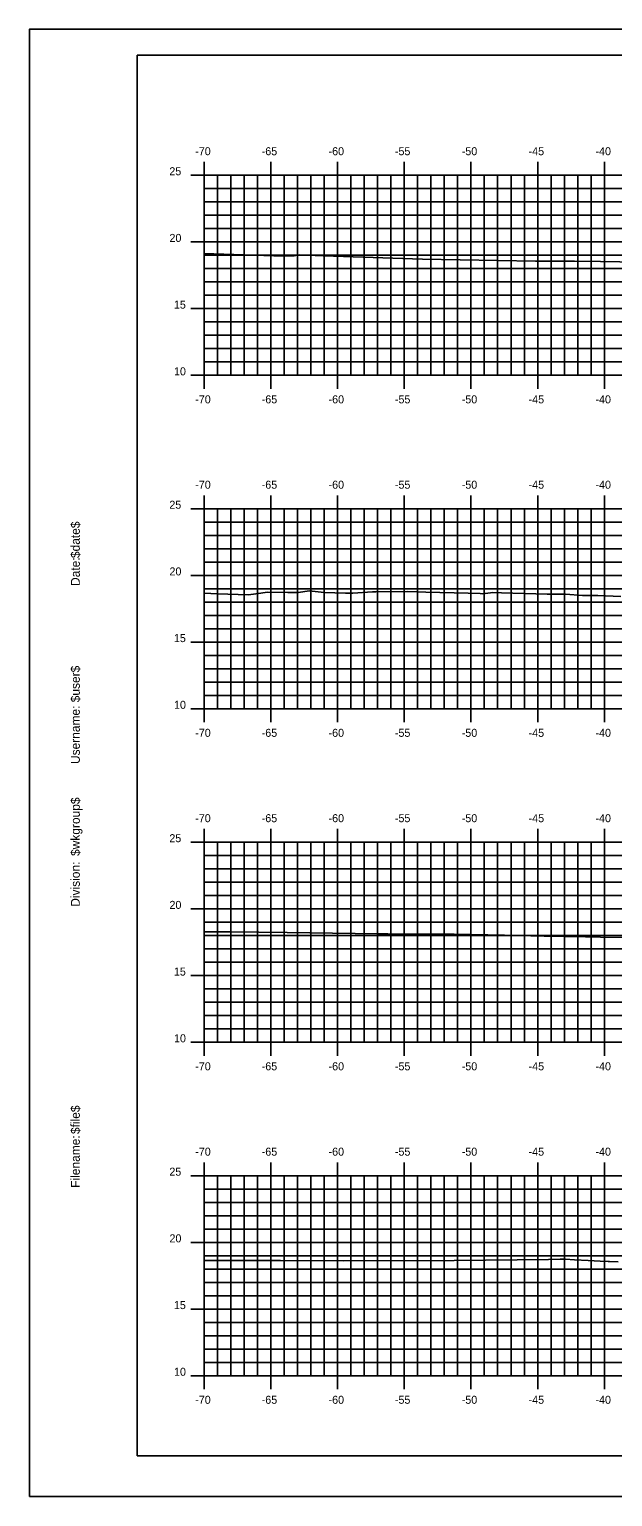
# Model space of a CAD drawing. Extents: x 1023237 to 1023407, y 394697 to 394807.
# Drawn here: x 1023236.6 to 1023280.3, y 394696.5 to 394806.5 of the extents above; entities that cross this region are included whole.
import ezdxf

# ---------------------------------------------------------------- set-up
doc = ezdxf.new("R2010")
doc.units = 0
for name, color, linetype in [('BORDER', 7, 'Continuous'), ('H_V ANNOTATION', 7, 'Continuous'), ('MAJOR', 7, 'Continuous'), ('MINOR', 7, 'Continuous'), ('PLOT BOUNDARY', 7, 'Continuous'), ('S_Roadway_Centerline', 7, 'Continuous')]:
    doc.layers.add(name, color=color, linetype=linetype)

msp = doc.modelspace()

# ---------------------------------------------------------------- linework, layer by layer
at = {"layer": 'BORDER'}
for p, q in [((1023404.66, 394804.61), (1023244.66, 394804.61)), ((1023244.66, 394804.61), (1023244.66, 394699.61)), ((1023244.66, 394699.61), (1023404.66, 394699.61))]:
    msp.add_line(p, q, dxfattribs=at)
at = {"layer": 'MAJOR'}
for p, q in [((1023249.66, 394796.61), (1023249.66, 394795.61)), ((1023254.66, 394796.61), (1023254.66, 394795.61)), ((1023259.66, 394796.61), (1023259.66, 394795.61)), ((1023264.66, 394796.61), (1023264.66, 394795.61)), ((1023269.66, 394796.61), (1023269.66, 394795.61)), ((1023274.66, 394796.61), (1023274.66, 394795.61)), ((1023279.66, 394796.61), (1023279.66, 394795.61)), ((1023248.66, 394795.61), (1023249.66, 394795.61)), ((1023249.66, 394795.61), (1023389.66, 394795.61)), ((1023249.66, 394780.61), (1023249.66, 394795.61)), ((1023254.66, 394780.61), (1023254.66, 394795.61)), ((1023259.66, 394780.61), (1023259.66, 394795.61)), ((1023264.66, 394780.61), (1023264.66, 394795.61)), ((1023269.66, 394780.61), (1023269.66, 394795.61)), ((1023274.66, 394780.61), (1023274.66, 394795.61)), ((1023279.66, 394780.61), (1023279.66, 394795.61)), ((1023248.66, 394790.61), (1023249.66, 394790.61)), ((1023249.66, 394790.61), (1023389.66, 394790.61)), ((1023248.66, 394785.61), (1023249.66, 394785.61)), ((1023249.66, 394785.61), (1023389.66, 394785.61)), ((1023248.66, 394780.61), (1023249.66, 394780.61)), ((1023249.66, 394780.61), (1023389.66, 394780.61)), ((1023249.66, 394779.6), (1023249.66, 394780.61)), ((1023254.66, 394779.6), (1023254.66, 394780.61)), ((1023259.66, 394779.6), (1023259.66, 394780.61)), ((1023264.66, 394779.6), (1023264.66, 394780.61)), ((1023269.66, 394779.6), (1023269.66, 394780.61)), ((1023274.66, 394779.6), (1023274.66, 394780.61)), ((1023279.66, 394779.6), (1023279.66, 394780.61)), ((1023249.66, 394771.61), (1023249.66, 394770.61)), ((1023254.66, 394771.61), (1023254.66, 394770.61)), ((1023259.66, 394771.61), (1023259.66, 394770.61)), ((1023264.66, 394771.61), (1023264.66, 394770.61)), ((1023269.66, 394771.61), (1023269.66, 394770.61)), ((1023274.66, 394771.61), (1023274.66, 394770.61)), ((1023279.66, 394771.61), (1023279.66, 394770.61)), ((1023248.66, 394770.61), (1023249.66, 394770.61)), ((1023249.66, 394770.61), (1023389.66, 394770.61)), ((1023249.66, 394755.61), (1023249.66, 394770.61)), ((1023254.66, 394755.61), (1023254.66, 394770.61)), ((1023259.66, 394755.61), (1023259.66, 394770.61)), ((1023264.66, 394755.61), (1023264.66, 394770.61)), ((1023269.66, 394755.61), (1023269.66, 394770.61)), ((1023274.66, 394755.61), (1023274.66, 394770.61)), ((1023279.66, 394755.61), (1023279.66, 394770.61)), ((1023248.66, 394765.61), (1023249.66, 394765.61)), ((1023249.66, 394765.61), (1023389.66, 394765.61)), ((1023248.66, 394760.61), (1023249.66, 394760.61)), ((1023249.66, 394760.61), (1023389.66, 394760.61)), ((1023248.66, 394755.61), (1023249.66, 394755.61)), ((1023249.66, 394755.61), (1023389.66, 394755.61)), ((1023249.66, 394754.6), (1023249.66, 394755.61)), ((1023254.66, 394754.6), (1023254.66, 394755.61)), ((1023259.66, 394754.6), (1023259.66, 394755.61)), ((1023264.66, 394754.6), (1023264.66, 394755.61)), ((1023269.66, 394754.6), (1023269.66, 394755.61)), ((1023274.66, 394754.6), (1023274.66, 394755.61)), ((1023279.66, 394754.6), (1023279.66, 394755.61)), ((1023249.66, 394746.61), (1023249.66, 394745.61)), ((1023254.66, 394746.61), (1023254.66, 394745.61)), ((1023259.66, 394746.61), (1023259.66, 394745.61)), ((1023264.66, 394746.61), (1023264.66, 394745.61)), ((1023269.66, 394746.61), (1023269.66, 394745.61)), ((1023274.66, 394746.61), (1023274.66, 394745.61)), ((1023279.66, 394746.61), (1023279.66, 394745.61)), ((1023248.66, 394745.61), (1023249.66, 394745.61)), ((1023249.66, 394745.61), (1023389.66, 394745.61)), ((1023249.66, 394730.61), (1023249.66, 394745.61)), ((1023254.66, 394730.61), (1023254.66, 394745.61)), ((1023259.66, 394730.61), (1023259.66, 394745.61)), ((1023264.66, 394730.61), (1023264.66, 394745.61)), ((1023269.66, 394730.61), (1023269.66, 394745.61)), ((1023274.66, 394730.61), (1023274.66, 394745.61)), ((1023279.66, 394730.61), (1023279.66, 394745.61)), ((1023248.66, 394740.61), (1023249.66, 394740.61)), ((1023249.66, 394740.61), (1023389.66, 394740.61)), ((1023248.66, 394735.61), (1023249.66, 394735.61)), ((1023249.66, 394735.61), (1023389.66, 394735.61)), ((1023248.66, 394730.61), (1023249.66, 394730.61)), ((1023249.66, 394730.61), (1023389.66, 394730.61)), ((1023249.66, 394729.6), (1023249.66, 394730.61)), ((1023254.66, 394729.6), (1023254.66, 394730.61)), ((1023259.66, 394729.6), (1023259.66, 394730.61)), ((1023264.66, 394729.6), (1023264.66, 394730.61)), ((1023269.66, 394729.6), (1023269.66, 394730.61)), ((1023274.66, 394729.6), (1023274.66, 394730.61)), ((1023279.66, 394729.6), (1023279.66, 394730.61)), ((1023249.66, 394721.61), (1023249.66, 394720.61)), ((1023254.66, 394721.61), (1023254.66, 394720.61)), ((1023259.66, 394721.61), (1023259.66, 394720.61)), ((1023264.66, 394721.61), (1023264.66, 394720.61)), ((1023269.66, 394721.61), (1023269.66, 394720.61)), ((1023274.66, 394721.61), (1023274.66, 394720.61)), ((1023279.66, 394721.61), (1023279.66, 394720.61)), ((1023248.66, 394720.61), (1023249.66, 394720.61)), ((1023249.66, 394720.61), (1023389.66, 394720.61)), ((1023249.66, 394705.61), (1023249.66, 394720.61)), ((1023254.66, 394705.61), (1023254.66, 394720.61)), ((1023259.66, 394705.61), (1023259.66, 394720.61)), ((1023264.66, 394705.61), (1023264.66, 394720.61)), ((1023269.66, 394705.61), (1023269.66, 394720.61)), ((1023274.66, 394705.61), (1023274.66, 394720.61)), ((1023279.66, 394705.61), (1023279.66, 394720.61)), ((1023248.66, 394715.61), (1023249.66, 394715.61)), ((1023249.66, 394715.61), (1023389.66, 394715.61)), ((1023248.66, 394710.61), (1023249.66, 394710.61)), ((1023249.66, 394710.61), (1023389.66, 394710.61)), ((1023248.66, 394705.61), (1023249.66, 394705.61)), ((1023249.66, 394705.61), (1023389.66, 394705.61)), ((1023249.66, 394704.6), (1023249.66, 394705.61)), ((1023254.66, 394704.6), (1023254.66, 394705.61)), ((1023259.66, 394704.6), (1023259.66, 394705.61)), ((1023264.66, 394704.6), (1023264.66, 394705.61)), ((1023269.66, 394704.6), (1023269.66, 394705.61)), ((1023274.66, 394704.6), (1023274.66, 394705.61)), ((1023279.66, 394704.6), (1023279.66, 394705.61))]:
    msp.add_line(p, q, dxfattribs=at)
at = {"layer": 'MINOR'}
for p, q in [((1023250.66, 394780.61), (1023250.66, 394795.61)), ((1023251.66, 394780.61), (1023251.66, 394795.61)), ((1023252.66, 394780.61), (1023252.66, 394795.61)), ((1023253.66, 394780.61), (1023253.66, 394795.61)), ((1023255.66, 394780.61), (1023255.66, 394795.61)), ((1023256.66, 394780.61), (1023256.66, 394795.61)), ((1023257.66, 394780.61), (1023257.66, 394795.61)), ((1023258.66, 394780.61), (1023258.66, 394795.61)), ((1023260.66, 394780.61), (1023260.66, 394795.61)), ((1023261.66, 394780.61), (1023261.66, 394795.61)), ((1023262.66, 394780.61), (1023262.66, 394795.61)), ((1023263.66, 394780.61), (1023263.66, 394795.61)), ((1023265.66, 394780.61), (1023265.66, 394795.61)), ((1023266.66, 394780.61), (1023266.66, 394795.61)), ((1023267.66, 394780.61), (1023267.66, 394795.61)), ((1023268.66, 394780.61), (1023268.66, 394795.61)), ((1023270.66, 394780.61), (1023270.66, 394795.61)), ((1023271.66, 394780.61), (1023271.66, 394795.61)), ((1023272.66, 394780.61), (1023272.66, 394795.61)), ((1023273.66, 394780.61), (1023273.66, 394795.61)), ((1023275.66, 394780.61), (1023275.66, 394795.61)), ((1023276.66, 394780.61), (1023276.66, 394795.61)), ((1023277.66, 394780.61), (1023277.66, 394795.61)), ((1023278.66, 394780.61), (1023278.66, 394795.61)), ((1023249.66, 394794.61), (1023389.66, 394794.61)), ((1023249.66, 394794.61), (1023250.67, 394794.61)), ((1023249.66, 394793.61), (1023389.66, 394793.61)), ((1023249.66, 394793.61), (1023250.67, 394793.61)), ((1023249.66, 394792.61), (1023389.66, 394792.61)), ((1023249.66, 394792.61), (1023250.67, 394792.61)), ((1023249.66, 394791.61), (1023389.66, 394791.61)), ((1023249.66, 394791.61), (1023250.67, 394791.61)), ((1023249.66, 394789.61), (1023389.66, 394789.61)), ((1023249.66, 394789.61), (1023250.67, 394789.61)), ((1023249.66, 394788.61), (1023389.66, 394788.61)), ((1023249.66, 394788.61), (1023250.67, 394788.61)), ((1023249.66, 394787.61), (1023389.66, 394787.61)), ((1023249.66, 394787.61), (1023250.67, 394787.61)), ((1023249.66, 394786.61), (1023389.66, 394786.61)), ((1023249.66, 394786.61), (1023250.67, 394786.61)), ((1023249.66, 394784.61), (1023389.66, 394784.61)), ((1023249.66, 394784.61), (1023250.67, 394784.61)), ((1023249.66, 394783.61), (1023389.66, 394783.61)), ((1023249.66, 394783.61), (1023250.67, 394783.61)), ((1023249.66, 394782.61), (1023389.66, 394782.61)), ((1023249.66, 394782.61), (1023250.67, 394782.61)), ((1023249.66, 394781.61), (1023389.66, 394781.61)), ((1023249.66, 394781.61), (1023250.67, 394781.61)), ((1023250.66, 394755.61), (1023250.66, 394770.61)), ((1023251.66, 394755.61), (1023251.66, 394770.61)), ((1023252.66, 394755.61), (1023252.66, 394770.61)), ((1023253.66, 394755.61), (1023253.66, 394770.61)), ((1023255.66, 394755.61), (1023255.66, 394770.61)), ((1023256.66, 394755.61), (1023256.66, 394770.61)), ((1023257.66, 394755.61), (1023257.66, 394770.61)), ((1023258.66, 394755.61), (1023258.66, 394770.61)), ((1023260.66, 394755.61), (1023260.66, 394770.61)), ((1023261.66, 394755.61), (1023261.66, 394770.61)), ((1023262.66, 394755.61), (1023262.66, 394770.61)), ((1023263.66, 394755.61), (1023263.66, 394770.61)), ((1023265.66, 394755.61), (1023265.66, 394770.61)), ((1023266.66, 394755.61), (1023266.66, 394770.61)), ((1023267.66, 394755.61), (1023267.66, 394770.61)), ((1023268.66, 394755.61), (1023268.66, 394770.61)), ((1023270.66, 394755.61), (1023270.66, 394770.61)), ((1023271.66, 394755.61), (1023271.66, 394770.61)), ((1023272.66, 394755.61), (1023272.66, 394770.61)), ((1023273.66, 394755.61), (1023273.66, 394770.61)), ((1023275.66, 394755.61), (1023275.66, 394770.61)), ((1023276.66, 394755.61), (1023276.66, 394770.61)), ((1023277.66, 394755.61), (1023277.66, 394770.61)), ((1023278.66, 394755.61), (1023278.66, 394770.61)), ((1023249.66, 394769.61), (1023389.66, 394769.61)), ((1023249.66, 394769.61), (1023250.67, 394769.61)), ((1023249.66, 394768.61), (1023389.66, 394768.61)), ((1023249.66, 394768.61), (1023250.67, 394768.61)), ((1023249.66, 394767.61), (1023389.66, 394767.61)), ((1023249.66, 394767.61), (1023250.67, 394767.61)), ((1023249.66, 394766.61), (1023389.66, 394766.61)), ((1023249.66, 394766.61), (1023250.67, 394766.61)), ((1023249.66, 394764.61), (1023389.66, 394764.61)), ((1023249.66, 394764.61), (1023250.67, 394764.61)), ((1023249.66, 394763.61), (1023389.66, 394763.61)), ((1023249.66, 394763.61), (1023250.67, 394763.61)), ((1023249.66, 394762.61), (1023389.66, 394762.61)), ((1023249.66, 394762.61), (1023250.67, 394762.61)), ((1023249.66, 394761.61), (1023389.66, 394761.61)), ((1023249.66, 394761.61), (1023250.67, 394761.61)), ((1023249.66, 394759.61), (1023389.66, 394759.61)), ((1023249.66, 394759.61), (1023250.67, 394759.61)), ((1023249.66, 394758.61), (1023389.66, 394758.61)), ((1023249.66, 394758.61), (1023250.67, 394758.61)), ((1023249.66, 394757.61), (1023389.66, 394757.61)), ((1023249.66, 394757.61), (1023250.67, 394757.61)), ((1023249.66, 394756.61), (1023389.66, 394756.61)), ((1023249.66, 394756.61), (1023250.67, 394756.61)), ((1023250.66, 394730.61), (1023250.66, 394745.61)), ((1023251.66, 394730.61), (1023251.66, 394745.61)), ((1023252.66, 394730.61), (1023252.66, 394745.61)), ((1023253.66, 394730.61), (1023253.66, 394745.61)), ((1023255.66, 394730.61), (1023255.66, 394745.61)), ((1023256.66, 394730.61), (1023256.66, 394745.61)), ((1023257.66, 394730.61), (1023257.66, 394745.61)), ((1023258.66, 394730.61), (1023258.66, 394745.61)), ((1023260.66, 394730.61), (1023260.66, 394745.61)), ((1023261.66, 394730.61), (1023261.66, 394745.61)), ((1023262.66, 394730.61), (1023262.66, 394745.61)), ((1023263.66, 394730.61), (1023263.66, 394745.61)), ((1023265.66, 394730.61), (1023265.66, 394745.61)), ((1023266.66, 394730.61), (1023266.66, 394745.61)), ((1023267.66, 394730.61), (1023267.66, 394745.61)), ((1023268.66, 394730.61), (1023268.66, 394745.61)), ((1023270.66, 394730.61), (1023270.66, 394745.61)), ((1023271.66, 394730.61), (1023271.66, 394745.61)), ((1023272.66, 394730.61), (1023272.66, 394745.61)), ((1023273.66, 394730.61), (1023273.66, 394745.61)), ((1023275.66, 394730.61), (1023275.66, 394745.61)), ((1023276.66, 394730.61), (1023276.66, 394745.61)), ((1023277.66, 394730.61), (1023277.66, 394745.61)), ((1023278.66, 394730.61), (1023278.66, 394745.61)), ((1023249.66, 394744.61), (1023389.66, 394744.61)), ((1023249.66, 394744.61), (1023250.67, 394744.61)), ((1023249.66, 394743.61), (1023389.66, 394743.61)), ((1023249.66, 394743.61), (1023250.67, 394743.61)), ((1023249.66, 394742.61), (1023389.66, 394742.61)), ((1023249.66, 394742.61), (1023250.67, 394742.61)), ((1023249.66, 394741.61), (1023389.66, 394741.61)), ((1023249.66, 394741.61), (1023250.67, 394741.61)), ((1023249.66, 394739.61), (1023389.66, 394739.61)), ((1023249.66, 394739.61), (1023250.67, 394739.61)), ((1023249.66, 394738.61), (1023389.66, 394738.61)), ((1023249.66, 394738.61), (1023250.67, 394738.61)), ((1023249.66, 394737.61), (1023389.66, 394737.61)), ((1023249.66, 394737.61), (1023250.67, 394737.61)), ((1023249.66, 394736.61), (1023389.66, 394736.61)), ((1023249.66, 394736.61), (1023250.67, 394736.61)), ((1023249.66, 394734.61), (1023389.66, 394734.61)), ((1023249.66, 394734.61), (1023250.67, 394734.61)), ((1023249.66, 394733.61), (1023389.66, 394733.61)), ((1023249.66, 394733.61), (1023250.67, 394733.61)), ((1023249.66, 394732.61), (1023389.66, 394732.61)), ((1023249.66, 394732.61), (1023250.67, 394732.61)), ((1023249.66, 394731.61), (1023389.66, 394731.61)), ((1023249.66, 394731.61), (1023250.67, 394731.61)), ((1023249.66, 394719.61), (1023389.66, 394719.61)), ((1023249.66, 394719.61), (1023250.67, 394719.61)), ((1023250.66, 394705.61), (1023250.66, 394720.61)), ((1023251.66, 394705.61), (1023251.66, 394720.61)), ((1023252.66, 394705.61), (1023252.66, 394720.61)), ((1023253.66, 394705.61), (1023253.66, 394720.61)), ((1023255.66, 394705.61), (1023255.66, 394720.61)), ((1023256.66, 394705.61), (1023256.66, 394720.61)), ((1023257.66, 394705.61), (1023257.66, 394720.61)), ((1023258.66, 394705.61), (1023258.66, 394720.61)), ((1023260.66, 394705.61), (1023260.66, 394720.61)), ((1023261.66, 394705.61), (1023261.66, 394720.61)), ((1023262.66, 394705.61), (1023262.66, 394720.61)), ((1023263.66, 394705.61), (1023263.66, 394720.61)), ((1023265.66, 394705.61), (1023265.66, 394720.61)), ((1023266.66, 394705.61), (1023266.66, 394720.61)), ((1023267.66, 394705.61), (1023267.66, 394720.61)), ((1023268.66, 394705.61), (1023268.66, 394720.61)), ((1023270.66, 394705.61), (1023270.66, 394720.61)), ((1023271.66, 394705.61), (1023271.66, 394720.61)), ((1023272.66, 394705.61), (1023272.66, 394720.61)), ((1023273.66, 394705.61), (1023273.66, 394720.61)), ((1023275.66, 394705.61), (1023275.66, 394720.61)), ((1023276.66, 394705.61), (1023276.66, 394720.61)), ((1023277.66, 394705.61), (1023277.66, 394720.61)), ((1023278.66, 394705.61), (1023278.66, 394720.61)), ((1023249.66, 394718.61), (1023389.66, 394718.61)), ((1023249.66, 394718.61), (1023250.67, 394718.61)), ((1023249.66, 394717.61), (1023389.66, 394717.61)), ((1023249.66, 394717.61), (1023250.67, 394717.61)), ((1023249.66, 394716.61), (1023389.66, 394716.61)), ((1023249.66, 394716.61), (1023250.67, 394716.61)), ((1023249.66, 394714.61), (1023389.66, 394714.61)), ((1023249.66, 394714.61), (1023250.67, 394714.61)), ((1023249.66, 394713.61), (1023389.66, 394713.61)), ((1023249.66, 394713.61), (1023250.67, 394713.61)), ((1023249.66, 394712.61), (1023389.66, 394712.61)), ((1023249.66, 394712.61), (1023250.67, 394712.61)), ((1023249.66, 394711.61), (1023389.66, 394711.61)), ((1023249.66, 394711.61), (1023250.67, 394711.61)), ((1023249.66, 394709.61), (1023389.66, 394709.61)), ((1023249.66, 394709.61), (1023250.67, 394709.61)), ((1023249.66, 394708.61), (1023389.66, 394708.61)), ((1023249.66, 394708.61), (1023250.67, 394708.61)), ((1023249.66, 394707.61), (1023389.66, 394707.61)), ((1023249.66, 394707.61), (1023250.67, 394707.61)), ((1023249.66, 394706.61), (1023389.66, 394706.61)), ((1023249.66, 394706.61), (1023250.67, 394706.61))]:
    msp.add_line(p, q, dxfattribs=at)
at = {"layer": 'PLOT BOUNDARY'}
msp.add_lwpolyline([(1023236.57, 394696.55), (1023406.57, 394696.55), (1023406.57, 394806.55), (1023236.57, 394806.55)], close=True, dxfattribs=at)
at = {"layer": 'S_Roadway_Centerline'}
for points in [[(1023249.66, 394789.73), (1023250.39, 394789.72), (1023255.65, 394789.54), (1023255.93, 394789.57), (1023256.4, 394789.57), (1023256.82, 394789.64), (1023258.59, 394789.56), (1023259.35, 394789.54), (1023266.04, 394789.33), (1023274.49, 394789.17), (1023276.94, 394789.17), (1023276.99, 394789.17), (1023277.19, 394789.17), (1023277.31, 394789.16), (1023277.42, 394789.16), (1023279.37, 394789.14), (1023282.27, 394789.09)], [(1023249.66, 394764.28), (1023250.66, 394764.24), (1023253, 394764.16), (1023253.92, 394764.29), (1023254.39, 394764.35), (1023255.93, 394764.33), (1023256.73, 394764.33), (1023257.53, 394764.45), (1023258.66, 394764.32), (1023260.26, 394764.29), (1023260.81, 394764.29), (1023262.29, 394764.38), (1023262.54, 394764.39), (1023264.91, 394764.4), (1023266.29, 394764.36), (1023269.44, 394764.27), (1023270.35, 394764.25), (1023270.53, 394764.24), (1023271.13, 394764.31), (1023271.24, 394764.32), (1023271.94, 394764.3), (1023275.36, 394764.21), (1023276.74, 394764.21), (1023278.01, 394764.11), (1023279.17, 394764.1), (1023280.89, 394764.02)], [(1023249.66, 394738.89), (1023251.63, 394738.88), (1023255.88, 394738.84), (1023262.68, 394738.74), (1023263.43, 394738.73), (1023268.4, 394738.72), (1023272.17, 394738.63), (1023275.15, 394738.57), (1023278.23, 394738.52), (1023279.36, 394738.5), (1023283.64, 394738.44)], [(1023249.66, 394714.26), (1023252.84, 394714.25), (1023255.39, 394714.24), (1023260.11, 394714.22), (1023268.41, 394714.24), (1023275.46, 394714.33), (1023276.35, 394714.35), (1023276.74, 394714.35), (1023277.42, 394714.31), (1023278.43, 394714.26), (1023279.33, 394714.19), (1023279.95, 394714.18), (1023279.95, 394714.18), (1023280.04, 394714.17), (1023280.7, 394714.16)]]:
    msp.add_lwpolyline(points, dxfattribs=at)

# ---------------------------------------------------------------- texts
at = {"layer": 'BORDER'}
for s, p in [('$date$', (1023240.35, 394766.91)), ('Date:', (1023240.35, 394764.82)), ('$user$', (1023240.35, 394756.1)), ('Username:', (1023240.35, 394751.47)), ('$wkgroup$', (1023240.35, 394744.58)), ('Division:', (1023240.35, 394740.77)), ('$file$', (1023240.35, 394723.73)), ('Filename:', (1023240.35, 394719.7))]:
    msp.add_text(s, height=0.67, rotation=90, dxfattribs=at).set_placement(p)
at = {"layer": 'H_V ANNOTATION'}
for s, p in [('-70', (1023249, 394797.11)), ('-65', (1023253.98, 394797.11)), ('-60', (1023258.99, 394797.11)), ('-55', (1023263.96, 394797.11)), ('-50', (1023268.97, 394797.11)), ('-45', (1023273.98, 394797.11)), ('-40', (1023278.99, 394797.11)), ('25', (1023247.06, 394795.61)), ('20', (1023247.07, 394790.61)), ('15', (1023247.4, 394785.61)), ('10', (1023247.41, 394780.61)), ('-70', (1023249, 394778.51)), ('-65', (1023253.98, 394778.51)), ('-60', (1023258.99, 394778.51)), ('-55', (1023263.96, 394778.51)), ('-50', (1023268.97, 394778.51)), ('-45', (1023273.98, 394778.51)), ('-40', (1023278.99, 394778.51)), ('-70', (1023249, 394772.11)), ('-65', (1023253.98, 394772.11)), ('-60', (1023258.99, 394772.11)), ('-55', (1023263.96, 394772.11)), ('-50', (1023268.97, 394772.11)), ('-45', (1023273.98, 394772.11)), ('-40', (1023278.99, 394772.11)), ('25', (1023247.06, 394770.61)), ('20', (1023247.07, 394765.61)), ('15', (1023247.4, 394760.61)), ('10', (1023247.41, 394755.61)), ('-70', (1023249, 394753.51)), ('-65', (1023253.98, 394753.51)), ('-60', (1023258.99, 394753.51)), ('-55', (1023263.96, 394753.51)), ('-50', (1023268.97, 394753.51)), ('-45', (1023273.98, 394753.51)), ('-40', (1023278.99, 394753.51)), ('-70', (1023249, 394747.11)), ('-65', (1023253.98, 394747.11)), ('-60', (1023258.99, 394747.11)), ('-55', (1023263.96, 394747.11)), ('-50', (1023268.97, 394747.11)), ('-45', (1023273.98, 394747.11)), ('-40', (1023278.99, 394747.11)), ('25', (1023247.06, 394745.61)), ('20', (1023247.07, 394740.61)), ('15', (1023247.4, 394735.61)), ('10', (1023247.41, 394730.61)), ('-70', (1023249, 394728.51)), ('-65', (1023253.98, 394728.51)), ('-60', (1023258.99, 394728.51)), ('-55', (1023263.96, 394728.51)), ('-50', (1023268.97, 394728.51)), ('-45', (1023273.98, 394728.51)), ('-40', (1023278.99, 394728.51)), ('-70', (1023249, 394722.11)), ('-65', (1023253.98, 394722.11)), ('-60', (1023258.99, 394722.11)), ('-55', (1023263.96, 394722.11)), ('-50', (1023268.97, 394722.11)), ('-45', (1023273.98, 394722.11)), ('-40', (1023278.99, 394722.11)), ('25', (1023247.06, 394720.61)), ('20', (1023247.07, 394715.61)), ('15', (1023247.4, 394710.61)), ('10', (1023247.41, 394705.61)), ('-70', (1023249, 394703.51)), ('-65', (1023253.98, 394703.51)), ('-60', (1023258.99, 394703.51)), ('-55', (1023263.96, 394703.51)), ('-50', (1023268.97, 394703.51)), ('-45', (1023273.98, 394703.51)), ('-40', (1023278.99, 394703.51))]:
    msp.add_text(s, height=0.6, dxfattribs=at).set_placement(p)

doc.saveas('drawing.dxf')
